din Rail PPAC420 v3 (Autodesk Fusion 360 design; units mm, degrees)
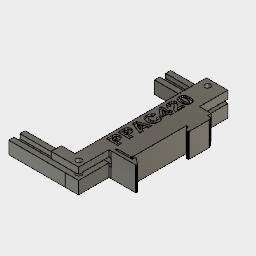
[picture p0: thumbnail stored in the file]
sketch "din_clip"
  line L1 (24.4607, 210.1295) -> (24.2926, 210.382)
  line L2 (-1.27, 219.4915) -> (-1.27, 209.4914)
  line L3 (19.7556, 279.4) -> (-1.27, 279.4)
  line L4 (-1.27, 210.2556) -> (-1.27, 190.3236)
  line L5 (18.3484, 212.746) -> (18.5627, 213.0637)
  line L6 (19.8915, 213.383) -> (19.8915, 211.4531)
  line L7 (-1.27, 258.0569) -> (19.7556, 258.0569)
  line L8 (22.4891, 257.9684) -> (22.0557, 258.6171)
  line L9 (9.0022, 211.6091) -> (8.8787, 211.953)
  line L10 (22.6413, 244.7031) -> (22.6413, 257.2029)
  line L11 (-1.27, 251.7434) -> (4.7097, 251.7434)
  line L12 (20.2976, 213.578) -> (20.0331, 213.6083)
  line L13 (24.2695, 209.5838) -> (24.4521, 209.826)
  line L14 (23.9801, 209.4914) -> (24.2695, 209.5838)
  line L15 (22.6413, 257.2029) -> (22.4891, 257.9684)
  line L16 (22.4949, 244.3496) -> (22.6413, 244.7031)
  line L17 (21.5847, 244.2032) -> (22.1415, 244.2032)
  line L18 (18.5627, 213.0637) -> (18.6412, 213.4529)
  line L19 (22.1415, 244.2032) -> (22.4949, 244.3496)
  line L20 (9.3591, 211.4531) -> (9.0022, 211.6091)
  line L21 (-1.27, 209.4914) -> (23.9801, 209.4914)
  line L22 (19.7556, 258.0569) -> (19.7556, 279.4)
  line L23 (21.0514, 244.3572) -> (21.5847, 244.2032)
  line L24 (-1.27, 279.4) -> (-1.27, 258.0569)
  line L25 (4.7097, 251.7434) -> (4.7099, 219.4915)
  line L26 (18.6412, 213.4529) -> (18.6412, 246.9531)
  line L27 (4.7099, 219.4915) -> (-1.27, 219.4915)
  line L28 (9.3591, 212.4532) -> (17.6415, 212.4532)
  line L29 (24.2926, 210.382) -> (20.2976, 213.578)
  line L30 (20.6821, 244.7723) -> (21.0514, 244.3572)
  line L31 (20.0331, 213.6083) -> (19.8915, 213.383)
  line L32 (22.0557, 258.6171) -> (21.4066, 259.0509)
  line L33 (7.2672, 190.3236) -> (7.2672, 210.2556)
  line L34 (18.0304, 212.5317) -> (18.3484, 212.746)
  line L35 (8.9953, 212.2968) -> (9.3591, 212.4532)
  line L36 (-1.27, 259.2036) -> (-1.27, 251.7434)
  line L37 (5.4884, 259.2031) -> (-1.27, 259.2036)
  line L38 (-1.27, 190.3236) -> (7.2672, 190.3236)
  line L39 (21.4066, 259.0509) -> (20.6415, 259.2031)
  line L40 (19.6414, 246.9531) -> (20.6821, 244.7723)
  line L41 (19.8915, 211.4531) -> (9.3591, 211.4531)
  line L42 (17.6415, 212.4532) -> (18.0304, 212.5317)
  line L43 (7.2672, 210.2556) -> (-1.27, 210.2556)
  line L44 (8.8787, 211.953) -> (8.9953, 212.2968)
  line L45 (20.6415, 259.2031) -> (5.4884, 259.2031)
  line L46 (18.6412, 246.9531) -> (19.6414, 246.9531)
  line L47 (24.4521, 209.826) -> (24.4607, 210.1295)
extrude "Extrude3" sketch "din_clip" blind 12.7
box_primitive "BoxPrimitive1" DistanceX 15.24 DistanceY 7.62 DistanceZ 3.81 OffsetDistanceX 0 OffsetDistanceY 0
step "MoveBody2"
step "MoveBody3"
step "MoveBody4"
offset_faces "OffsetFaces1" distance 6.096
combine "Combine3"
box_primitive "BoxPrimitive2" DistanceX 15.24 DistanceY 12.7 DistanceZ 7.62 OffsetDistanceX -7.62 OffsetDistanceY 12.7
step "MoveBody5"
offset_faces "OffsetFaces2" distance 15.24
combine "Combine6"
box_primitive "BoxPrimitive3" DistanceX 28.448 DistanceY 0.8719 DistanceZ 15.24 OffsetDistanceX 0 OffsetDistanceY 0
step "MoveBody13"
step "MoveBody14"
combine "Combine9"
box_primitive "BoxPrimitive4" DistanceX 15.24 DistanceY 7.62 DistanceZ 17.78 OffsetDistanceX 2.54 OffsetDistanceY 0
step "MoveBody15"
copy_paste_bodies "CopyPasteBodies2"
step "MoveBody16"
combine "Combine11"
step "MoveBody17"
step "MoveBody18"
offset_faces "OffsetFaces4" distance -1.27
copy_paste_bodies "CopyPasteBodies3"
step "MoveBody19"
offset_faces "OffsetFaces5" distance 25.4
combine "Combine12"
step "MoveBody20"
step "MoveBody21"
combine "Combine13"
offset_faces "OffsetFaces8" distance 6.35
offset_faces "OffsetFaces11" distance 2.54
box_primitive "BoxPrimitive5" DistanceX 2.54 DistanceY 20.32 DistanceZ 17.78 OffsetDistanceX 2.54 OffsetDistanceY -10.16
step "MoveBody22"
step "MoveBody23"
step "MoveBody24"
step "MoveBody25"
step "MoveBody26"
combine "Combine14"
offset_faces "OffsetFaces16" distance 1.27
box_primitive "BoxPrimitive6" DistanceX 2.54 DistanceY 5.08 DistanceZ 12.7 OffsetDistanceX -5.08 OffsetDistanceY 0
offset_faces "OffsetFaces31" distance 7.62
box_primitive "BoxPrimitive14" DistanceX 1.778 DistanceY 10.16 DistanceZ 99.06 OffsetDistanceX 0 OffsetDistanceY 0
step "MoveBody34"
step "MoveBody35"
combine "Combine15"
cylinder_primitive "CylinderPrimitive2" Height 17.78 Diameter 3.556
step "MoveBody36"
step "MoveBody37"
step "MoveBody38"
step "MoveBody39"
combine "Combine16"
step "MoveBody40"
combine "Combine17"
offset_faces "OffsetFaces34" distance 2.54
offset_faces "OffsetFaces35" distance 2.54
offset_faces "OffsetFaces36" distance -2.54
offset_faces "OffsetFaces37" distance -2.54
offset_faces "OffsetFaces38" distance -2.54
offset_faces "OffsetFaces39" distance -2.54
offset_faces "OffsetFaces40" distance -2.286
offset_faces "OffsetFaces41" distance -2.286
offset_faces "OffsetFaces42" distance 2.54
box_primitive "BoxPrimitive16" DistanceX 8.001 DistanceY 6.35 DistanceZ 12.7 OffsetDistanceX 0 OffsetDistanceY 0
box_primitive "BoxPrimitive26" DistanceX 5.461 DistanceY 6.35 DistanceZ 12.7 OffsetDistanceX 0 OffsetDistanceY 0
box_primitive "BoxPrimitive27" DistanceX 25.4 DistanceY 7.3819 DistanceZ -6.35 OffsetDistanceX 0 OffsetDistanceY 0
box_primitive "BoxPrimitive28" DistanceX 1.778 DistanceY 17.78 DistanceZ -5.08 OffsetDistanceX 0 OffsetDistanceY 0
offset_faces "OffsetFaces43" distance -2.54
offset_faces "OffsetFaces44" distance -2.54
offset_faces "OffsetFaces45" distance -1.27
offset_faces "OffsetFaces46" distance -1.27
box_primitive "BoxPrimitive22" DistanceX 6.35 DistanceY 2.54 DistanceZ 7.62 OffsetDistanceX 1.27 OffsetDistanceY 0
step "MoveBody43"
step "MoveBody44"
step "MoveBody45"
offset_faces "OffsetFaces47" distance 6.35
step "MoveBody46"
combine "Combine21"
box_primitive "BoxPrimitive23" DistanceX 5.461 DistanceY 2.54 DistanceZ 7.62 OffsetDistanceX 0 OffsetDistanceY 0
combine "Combine22"
box_primitive "BoxPrimitive24" DistanceX 7 DistanceY 8.784 DistanceZ 38.1 OffsetDistanceX 0 OffsetDistanceY 0
box_primitive "BoxPrimitive25" DistanceX 0.254 DistanceY 50.8 DistanceZ 101.6 OffsetDistanceX 2.4765 OffsetDistanceY 0
step "MoveBody68"
combine "Combine30"
step "MoveBody69"
offset_faces "OffsetFaces49" distance 2.54
sketch "Sketch48"
  curve K1 (4.9025, 16.1997) -> (4.9025, -32.6773)
  curve K2 (-5.0975, 16.1997) -> (4.9025, 16.1997)
  curve K3 (-5.0975, -32.6773) -> (-5.0975, 16.1997)
  curve K4 (4.9025, -32.6773) -> (-5.0975, -32.6773)
extrude "Extrude4" new body sketch "Sketch48" blind 1.27
box_primitive "BoxPrimitive29" DistanceX 49 DistanceY 7.565 DistanceZ 0.1 OffsetDistanceX 0 OffsetDistanceY 0
combine "Combine45"
offset_faces "OffsetFaces61" distance 8
offset_faces "OffsetFaces62" distance 57
move "Move10"
combine "Combine43"
box_primitive "BoxPrimitive32" DistanceX 5 DistanceY 51.8922 DistanceZ -10 OffsetDistanceX 0 OffsetDistanceY 0
offset_faces "OffsetFaces63" distance 4
offset_faces "OffsetFaces64" distance 38.2
step "MoveBody71"
step "MoveBody87"
offset_faces "OffsetFaces53" distance -0.508
offset_faces "OffsetFaces57" distance 10
offset_faces "OffsetFaces58" distance 4
box_primitive "BoxPrimitive31" DistanceX 2.825 DistanceY 3.778 DistanceZ -14 OffsetDistanceX 0 OffsetDistanceY -1
move_face "MoveFace2"
move "Move3"
move_face "MoveFace3"
move "Move4"
move "Move5"
move "Move6"
move "Move7"
move "Move8"
offset_faces "OffsetFaces59" distance -4
move "Move9"
combine "Combine44"
box_primitive "BoxPrimitive33" DistanceX 3.2 DistanceY 89.0764 DistanceZ -9 OffsetDistanceX 0 OffsetDistanceY 0
offset_faces "OffsetFaces65" distance 10
move "Move13"
combine "Combine46"
box_primitive "BoxPrimitive34" DistanceX 10.397 DistanceY 0.1502 DistanceZ -8.5 OffsetDistanceX 0 OffsetDistanceY 0
move "Move14"
copy_paste_bodies "CopyPasteBodies6"
move "Move15"
move "Move16"
move "Move17"
combine "Combine47"
move "Move18"
combine "Combine48"
offset_faces "OffsetFaces66" distance 13
offset_faces "OffsetFaces67" distance -9
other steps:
base_feature "Base Feature2"
base_feature "Base Feature3"
base_feature "Base Feature6"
